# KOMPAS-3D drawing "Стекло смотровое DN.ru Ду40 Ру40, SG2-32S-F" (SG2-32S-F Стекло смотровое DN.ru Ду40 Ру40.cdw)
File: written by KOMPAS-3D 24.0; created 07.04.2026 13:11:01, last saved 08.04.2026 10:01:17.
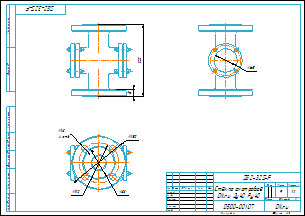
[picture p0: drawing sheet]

Document properties: Автор: Main; Форматы листов документа: A3; Полное имя файла: SG2-32S-F Стекло смотровое DN.ru Ду40 Ру40.m3d; Масса: 9; Наименование: Стекло смотровое DN.ru Ду40 Ру40; Количество листов документа: 1; Примечание: D500-00107

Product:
- Body: Тело 1  | qty 1
    Масса: 7.458074
- Part/product: Стекло смотровое DN.ru Ду40 Ру40  | designation SG2-32S-F
    Масса: 9
    Раздел спецификации: Прочие изделия
    Примечание: D500-00107

Views: Вид 1, Снизу, Проекционный вид 2
Referenced files in D:\DN.ru Аутсерс\Стекло смотровое DN.ru\Стекло смотровое DN.ru SG2-34G-F тип В ГОСТ 21836-2021 Ду100 Ру16, углеродистая сталь, фланцевое\: SG2-34G-F тип В Стекло смотровое DN.ru Ду100 Ру16.m3d, SG2-34G-F тип ВСтекло смотровое DN.ru Ду100 Ру16.cdw
Referenced files in D:\DN.ru Аутсерс\Стекло смотровое DN.ru\SG2-32S-F Стекло смотровое DN.ru Ду40 Ру40\: SG2-32S-F Стекло смотровое DN.ru Ду40 Ру40.m3d
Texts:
  SG2-32S-F
  Стекло смотровое
  DN.ru Ду40 Ру40
  Стекло смотровое DN.ru Ду40 Ру40
  SG2-32S-F Стекло смотровое DN.ru Ду40 Ру40
Dimensions and other numbers on the sheet: 0; 3; 2; 4; 200; 18; 150; 4 отв.; 88; 110; 1:2; 1; 9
